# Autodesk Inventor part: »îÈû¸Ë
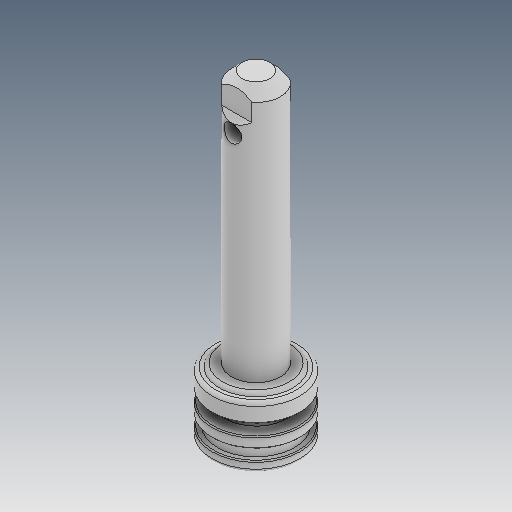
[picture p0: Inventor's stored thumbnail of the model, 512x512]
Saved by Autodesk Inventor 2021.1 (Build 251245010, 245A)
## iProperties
Created: 2015-08
Part Number: »îÈû¸Ë
Material: Ogólny
Document SubType Name: Modeling
Designer: user
Density: 1 g/cm^3
Appearance: Domyślna
Author: user
Revision Number: ÈÎºÎ
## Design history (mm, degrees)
feature "ÇÐ³ý-Ðý×ª1"
node "Bryła1"
